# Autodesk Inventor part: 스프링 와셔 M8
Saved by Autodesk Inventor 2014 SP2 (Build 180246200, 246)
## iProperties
Created: 2025-07
Part Number: 스프링 와셔 M8
Material: Generic
Document SubType Name: Modeling
Designer: Administrator
Density: 1 g/cm^3
Appearance: Default
Author: Administrator
Author: jhkim
Description: 스프링 잠금 와셔
Creation Date: 2025-06-11
Sending System: Autodesk Inventor 2026
Preprocessor: ST-DEVELOPER v20.1
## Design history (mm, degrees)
node "스프링 와셔 M81"
body "Solid1"
node "기준1"
